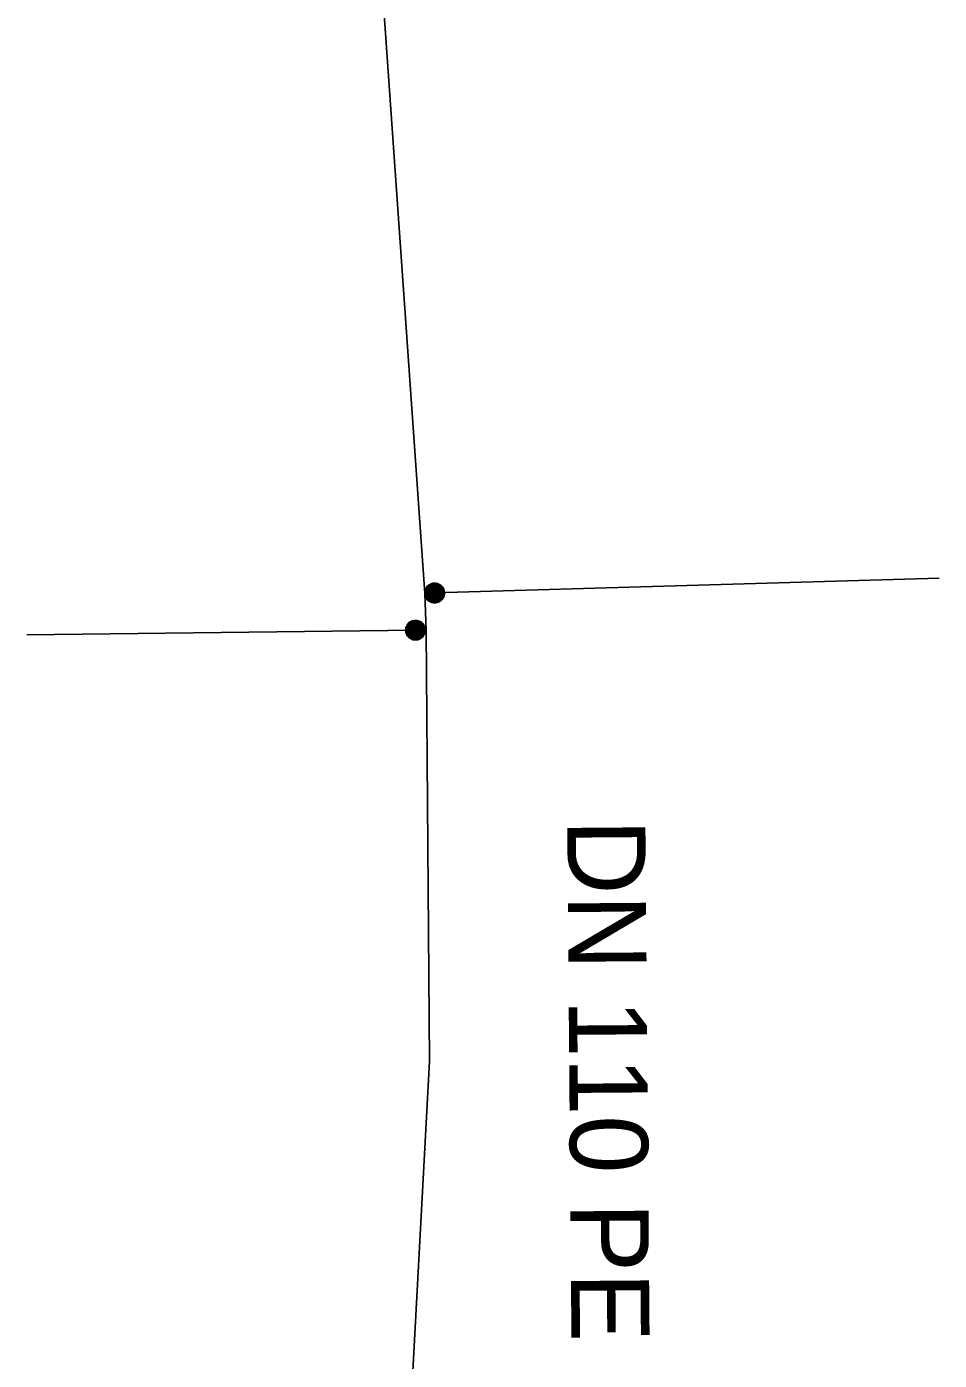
# Model space of a CAD drawing. Extents: x -832382 to -831581, y -1074670 to -1074251.
# Drawn here: x -831897.95 to -831874.6, y -1074363.15 to -1074329.02 of the extents above; entities that cross this region are included whole.
import ezdxf

# ---------------------------------------------------------------- set-up
doc = ezdxf.new("R2010")
doc.units = 0
for name, color, linetype in [('Přípojka vodovodu', 7, 'Continuous'), ('Přípojkový uzávěr', 7, 'Continuous'), ('Roz-řad', 7, 'Continuous'), ('Roz-řad-popis základní', 7, 'Continuous')]:
    doc.layers.add(name, color=color, linetype=linetype)

msp = doc.modelspace()

# ---------------------------------------------------------------- linework, layer by layer
at = {"layer": 'Přípojka vodovodu'}
for points in [[(-831887.76, -1074343.52), (-831887.51, -1074343.51), (-831874.597, -1074343.131)], [(-831887.73, -1074344.47), (-831888, -1074344.46), (-831897.947, -1074344.577)]]:
    msp.add_lwpolyline(points, dxfattribs=at)
at = {"layer": 'Přípojkový uzávěr'}
for points in [[(-831887.51, -1074343.26), (-831887.447, -1074343.26), (-831887.387, -1074343.292), (-831887.328, -1074343.324), (-831887.294, -1074343.385), (-831887.26, -1074343.445), (-831887.26, -1074343.51), (-831887.26, -1074343.575), (-831887.293, -1074343.635), (-831887.326, -1074343.694), (-831887.385, -1074343.727), (-831887.445, -1074343.76), (-831887.51, -1074343.76), (-831887.575, -1074343.76), (-831887.635, -1074343.727), (-831887.694, -1074343.694), (-831887.727, -1074343.635), (-831887.76, -1074343.575), (-831887.76, -1074343.51), (-831887.76, -1074343.445), (-831887.726, -1074343.385), (-831887.693, -1074343.324), (-831887.633, -1074343.292), (-831887.573, -1074343.26), (-831887.51, -1074343.26)], [(-831887.51, -1074343.283), (-831887.567, -1074343.283), (-831887.622, -1074343.313), (-831887.676, -1074343.342), (-831887.706, -1074343.396), (-831887.737, -1074343.451), (-831887.737, -1074343.51), (-831887.737, -1074343.569), (-831887.707, -1074343.623), (-831887.677, -1074343.677), (-831887.623, -1074343.707), (-831887.569, -1074343.737), (-831887.51, -1074343.737), (-831887.451, -1074343.737), (-831887.397, -1074343.707), (-831887.343, -1074343.677), (-831887.313, -1074343.623), (-831887.283, -1074343.569), (-831887.283, -1074343.51), (-831887.283, -1074343.451), (-831887.314, -1074343.396), (-831887.345, -1074343.342), (-831887.399, -1074343.313), (-831887.453, -1074343.283), (-831887.51, -1074343.283)], [(-831887.51, -1074343.301), (-831887.457, -1074343.301), (-831887.407, -1074343.328), (-831887.357, -1074343.354), (-831887.329, -1074343.405), (-831887.301, -1074343.455), (-831887.301, -1074343.51), (-831887.301, -1074343.565), (-831887.328, -1074343.614), (-831887.355, -1074343.664), (-831887.406, -1074343.692), (-831887.456, -1074343.719), (-831887.51, -1074343.719), (-831887.564, -1074343.719), (-831887.614, -1074343.692), (-831887.665, -1074343.664), (-831887.692, -1074343.614), (-831887.719, -1074343.565), (-831887.719, -1074343.51), (-831887.719, -1074343.455), (-831887.691, -1074343.405), (-831887.663, -1074343.354), (-831887.613, -1074343.328), (-831887.563, -1074343.301), (-831887.51, -1074343.301)], [(-831887.51, -1074343.323), (-831887.589, -1074343.323), (-831887.643, -1074343.377), (-831887.698, -1074343.432), (-831887.698, -1074343.51), (-831887.698, -1074343.588), (-831887.643, -1074343.643), (-831887.588, -1074343.698), (-831887.51, -1074343.698), (-831887.432, -1074343.698), (-831887.377, -1074343.643), (-831887.323, -1074343.588), (-831887.323, -1074343.51), (-831887.323, -1074343.432), (-831887.377, -1074343.377), (-831887.432, -1074343.323), (-831887.51, -1074343.323)], [(-831887.51, -1074343.345), (-831887.442, -1074343.345), (-831887.394, -1074343.393), (-831887.346, -1074343.441), (-831887.346, -1074343.51), (-831887.346, -1074343.578), (-831887.394, -1074343.626), (-831887.442, -1074343.674), (-831887.51, -1074343.674), (-831887.579, -1074343.674), (-831887.627, -1074343.626), (-831887.675, -1074343.578), (-831887.675, -1074343.51), (-831887.675, -1074343.441), (-831887.627, -1074343.393), (-831887.579, -1074343.345), (-831887.51, -1074343.345)], [(-831887.51, -1074343.365), (-831887.571, -1074343.365), (-831887.613, -1074343.407), (-831887.655, -1074343.45), (-831887.655, -1074343.51), (-831887.655, -1074343.569), (-831887.613, -1074343.612), (-831887.571, -1074343.654), (-831887.51, -1074343.654), (-831887.451, -1074343.654), (-831887.408, -1074343.612), (-831887.366, -1074343.569), (-831887.366, -1074343.51), (-831887.366, -1074343.45), (-831887.408, -1074343.407), (-831887.45, -1074343.365), (-831887.51, -1074343.365)], [(-831887.51, -1074343.385), (-831887.458, -1074343.385), (-831887.421, -1074343.422), (-831887.385, -1074343.458), (-831887.385, -1074343.51), (-831887.385, -1074343.562), (-831887.422, -1074343.599), (-831887.458, -1074343.635), (-831887.51, -1074343.635), (-831887.562, -1074343.635), (-831887.598, -1074343.599), (-831887.635, -1074343.562), (-831887.635, -1074343.51), (-831887.635, -1074343.458), (-831887.599, -1074343.422), (-831887.562, -1074343.385), (-831887.51, -1074343.385)], [(-831887.51, -1074343.408), (-831887.552, -1074343.408), (-831887.582, -1074343.438), (-831887.612, -1074343.468), (-831887.612, -1074343.51), (-831887.612, -1074343.552), (-831887.582, -1074343.582), (-831887.552, -1074343.611), (-831887.51, -1074343.611), (-831887.468, -1074343.611), (-831887.438, -1074343.582), (-831887.409, -1074343.552), (-831887.409, -1074343.51), (-831887.409, -1074343.468), (-831887.438, -1074343.438), (-831887.468, -1074343.408), (-831887.51, -1074343.408)], [(-831887.51, -1074343.426), (-831887.475, -1074343.426), (-831887.451, -1074343.45), (-831887.426, -1074343.475), (-831887.426, -1074343.51), (-831887.426, -1074343.545), (-831887.451, -1074343.569), (-831887.475, -1074343.594), (-831887.51, -1074343.594), (-831887.545, -1074343.594), (-831887.57, -1074343.569), (-831887.594, -1074343.545), (-831887.594, -1074343.51), (-831887.594, -1074343.475), (-831887.57, -1074343.45), (-831887.545, -1074343.426), (-831887.51, -1074343.426)], [(-831887.51, -1074343.448), (-831887.536, -1074343.448), (-831887.554, -1074343.466), (-831887.573, -1074343.484), (-831887.573, -1074343.51), (-831887.573, -1074343.536), (-831887.554, -1074343.554), (-831887.536, -1074343.573), (-831887.51, -1074343.573), (-831887.484, -1074343.573), (-831887.466, -1074343.554), (-831887.448, -1074343.536), (-831887.448, -1074343.51), (-831887.448, -1074343.484), (-831887.466, -1074343.466), (-831887.484, -1074343.448), (-831887.51, -1074343.448)], [(-831887.51, -1074343.471), (-831887.494, -1074343.471), (-831887.482, -1074343.482), (-831887.471, -1074343.493), (-831887.471, -1074343.51), (-831887.471, -1074343.526), (-831887.482, -1074343.538), (-831887.494, -1074343.549), (-831887.51, -1074343.549), (-831887.526, -1074343.549), (-831887.538, -1074343.538), (-831887.549, -1074343.526), (-831887.549, -1074343.51), (-831887.549, -1074343.493), (-831887.538, -1074343.482), (-831887.526, -1074343.471), (-831887.51, -1074343.471)], [(-831887.51, -1074343.487), (-831887.52, -1074343.487), (-831887.527, -1074343.493), (-831887.534, -1074343.5), (-831887.534, -1074343.51), (-831887.534, -1074343.52), (-831887.527, -1074343.527), (-831887.52, -1074343.533), (-831887.51, -1074343.533), (-831887.5, -1074343.533), (-831887.494, -1074343.527), (-831887.487, -1074343.52), (-831887.487, -1074343.51), (-831887.487, -1074343.5), (-831887.494, -1074343.493), (-831887.5, -1074343.487), (-831887.51, -1074343.487)], [(-831888, -1074344.21), (-831887.937, -1074344.21), (-831887.877, -1074344.242), (-831887.818, -1074344.274), (-831887.784, -1074344.335), (-831887.75, -1074344.395), (-831887.75, -1074344.46), (-831887.75, -1074344.525), (-831887.783, -1074344.585), (-831887.816, -1074344.644), (-831887.875, -1074344.677), (-831887.935, -1074344.71), (-831888, -1074344.71), (-831888.065, -1074344.71), (-831888.125, -1074344.677), (-831888.184, -1074344.644), (-831888.217, -1074344.585), (-831888.25, -1074344.525), (-831888.25, -1074344.46), (-831888.25, -1074344.395), (-831888.216, -1074344.335), (-831888.183, -1074344.274), (-831888.123, -1074344.242), (-831888.063, -1074344.21), (-831888, -1074344.21)], [(-831888, -1074344.233), (-831888.057, -1074344.233), (-831888.112, -1074344.263), (-831888.166, -1074344.292), (-831888.196, -1074344.346), (-831888.227, -1074344.401), (-831888.227, -1074344.46), (-831888.227, -1074344.519), (-831888.197, -1074344.573), (-831888.167, -1074344.627), (-831888.113, -1074344.657), (-831888.059, -1074344.687), (-831888, -1074344.687), (-831887.941, -1074344.687), (-831887.887, -1074344.657), (-831887.833, -1074344.627), (-831887.803, -1074344.573), (-831887.773, -1074344.519), (-831887.773, -1074344.46), (-831887.773, -1074344.401), (-831887.804, -1074344.346), (-831887.835, -1074344.292), (-831887.889, -1074344.263), (-831887.943, -1074344.233), (-831888, -1074344.233)], [(-831888, -1074344.251), (-831887.947, -1074344.251), (-831887.897, -1074344.278), (-831887.847, -1074344.304), (-831887.819, -1074344.355), (-831887.791, -1074344.405), (-831887.791, -1074344.46), (-831887.791, -1074344.515), (-831887.818, -1074344.564), (-831887.845, -1074344.614), (-831887.896, -1074344.642), (-831887.946, -1074344.669), (-831888, -1074344.669), (-831888.054, -1074344.669), (-831888.104, -1074344.642), (-831888.155, -1074344.614), (-831888.182, -1074344.564), (-831888.209, -1074344.515), (-831888.209, -1074344.46), (-831888.209, -1074344.405), (-831888.181, -1074344.355), (-831888.153, -1074344.304), (-831888.103, -1074344.278), (-831888.053, -1074344.251), (-831888, -1074344.251)], [(-831888, -1074344.273), (-831888.079, -1074344.273), (-831888.133, -1074344.327), (-831888.188, -1074344.382), (-831888.188, -1074344.46), (-831888.188, -1074344.538), (-831888.133, -1074344.593), (-831888.078, -1074344.648), (-831888, -1074344.648), (-831887.922, -1074344.648), (-831887.867, -1074344.593), (-831887.813, -1074344.538), (-831887.813, -1074344.46), (-831887.813, -1074344.382), (-831887.867, -1074344.327), (-831887.922, -1074344.273), (-831888, -1074344.273)], [(-831888, -1074344.295), (-831887.932, -1074344.295), (-831887.884, -1074344.343), (-831887.836, -1074344.391), (-831887.836, -1074344.46), (-831887.836, -1074344.528), (-831887.884, -1074344.576), (-831887.932, -1074344.624), (-831888, -1074344.624), (-831888.069, -1074344.624), (-831888.117, -1074344.576), (-831888.165, -1074344.528), (-831888.165, -1074344.46), (-831888.165, -1074344.391), (-831888.117, -1074344.343), (-831888.069, -1074344.295), (-831888, -1074344.295)], [(-831888, -1074344.315), (-831888.061, -1074344.315), (-831888.103, -1074344.357), (-831888.145, -1074344.4), (-831888.145, -1074344.46), (-831888.145, -1074344.519), (-831888.103, -1074344.562), (-831888.061, -1074344.604), (-831888, -1074344.604), (-831887.941, -1074344.604), (-831887.898, -1074344.562), (-831887.856, -1074344.519), (-831887.856, -1074344.46), (-831887.856, -1074344.4), (-831887.898, -1074344.357), (-831887.94, -1074344.315), (-831888, -1074344.315)], [(-831888, -1074344.335), (-831887.948, -1074344.335), (-831887.911, -1074344.372), (-831887.875, -1074344.408), (-831887.875, -1074344.46), (-831887.875, -1074344.512), (-831887.912, -1074344.549), (-831887.948, -1074344.585), (-831888, -1074344.585), (-831888.052, -1074344.585), (-831888.088, -1074344.549), (-831888.125, -1074344.512), (-831888.125, -1074344.46), (-831888.125, -1074344.408), (-831888.089, -1074344.372), (-831888.052, -1074344.335), (-831888, -1074344.335)], [(-831888, -1074344.358), (-831888.042, -1074344.358), (-831888.072, -1074344.388), (-831888.102, -1074344.418), (-831888.102, -1074344.46), (-831888.102, -1074344.502), (-831888.072, -1074344.532), (-831888.042, -1074344.561), (-831888, -1074344.561), (-831887.958, -1074344.561), (-831887.928, -1074344.532), (-831887.899, -1074344.502), (-831887.899, -1074344.46), (-831887.899, -1074344.418), (-831887.928, -1074344.388), (-831887.958, -1074344.358), (-831888, -1074344.358)], [(-831888, -1074344.376), (-831887.965, -1074344.376), (-831887.941, -1074344.4), (-831887.916, -1074344.425), (-831887.916, -1074344.46), (-831887.916, -1074344.495), (-831887.941, -1074344.519), (-831887.965, -1074344.544), (-831888, -1074344.544), (-831888.035, -1074344.544), (-831888.06, -1074344.519), (-831888.084, -1074344.495), (-831888.084, -1074344.46), (-831888.084, -1074344.425), (-831888.06, -1074344.4), (-831888.035, -1074344.376), (-831888, -1074344.376)], [(-831888, -1074344.398), (-831888.026, -1074344.398), (-831888.044, -1074344.416), (-831888.063, -1074344.434), (-831888.063, -1074344.46), (-831888.063, -1074344.486), (-831888.044, -1074344.504), (-831888.026, -1074344.523), (-831888, -1074344.523), (-831887.974, -1074344.523), (-831887.956, -1074344.504), (-831887.938, -1074344.486), (-831887.938, -1074344.46), (-831887.938, -1074344.434), (-831887.956, -1074344.416), (-831887.974, -1074344.398), (-831888, -1074344.398)], [(-831888, -1074344.421), (-831887.984, -1074344.421), (-831887.972, -1074344.432), (-831887.961, -1074344.443), (-831887.961, -1074344.46), (-831887.961, -1074344.476), (-831887.972, -1074344.488), (-831887.984, -1074344.499), (-831888, -1074344.499), (-831888.016, -1074344.499), (-831888.028, -1074344.488), (-831888.039, -1074344.476), (-831888.039, -1074344.46), (-831888.039, -1074344.443), (-831888.028, -1074344.432), (-831888.016, -1074344.421), (-831888, -1074344.421)], [(-831888, -1074344.437), (-831888.01, -1074344.437), (-831888.017, -1074344.443), (-831888.024, -1074344.45), (-831888.024, -1074344.46), (-831888.024, -1074344.47), (-831888.017, -1074344.477), (-831888.01, -1074344.483), (-831888, -1074344.483), (-831887.99, -1074344.483), (-831887.984, -1074344.477), (-831887.977, -1074344.47), (-831887.977, -1074344.46), (-831887.977, -1074344.45), (-831887.984, -1074344.443), (-831887.99, -1074344.437), (-831888, -1074344.437)]]:
    msp.add_open_spline(points, degree=3, dxfattribs=at)
at = {"layer": 'Roz-řad'}
msp.add_lwpolyline([(-831886.3, -1074408.64), (-831880.97, -1074408.01), (-831882.036, -1074380.258), (-831888.259, -1074367.098), (-831888.249, -1074366.757), (-831887.64, -1074355.49), (-831887.73, -1074344.47), (-831887.76, -1074343.52), (-831889.32, -1074321.29)], dxfattribs=at)

# ---------------------------------------------------------------- texts
at = {"layer": 'Roz-řad-popis základní'}
msp.add_text('DN 110 PE', height=2, rotation=270.4679, dxfattribs=at).set_placement((-831884.118, -1074349.303))

doc.saveas('drawing.dxf')
